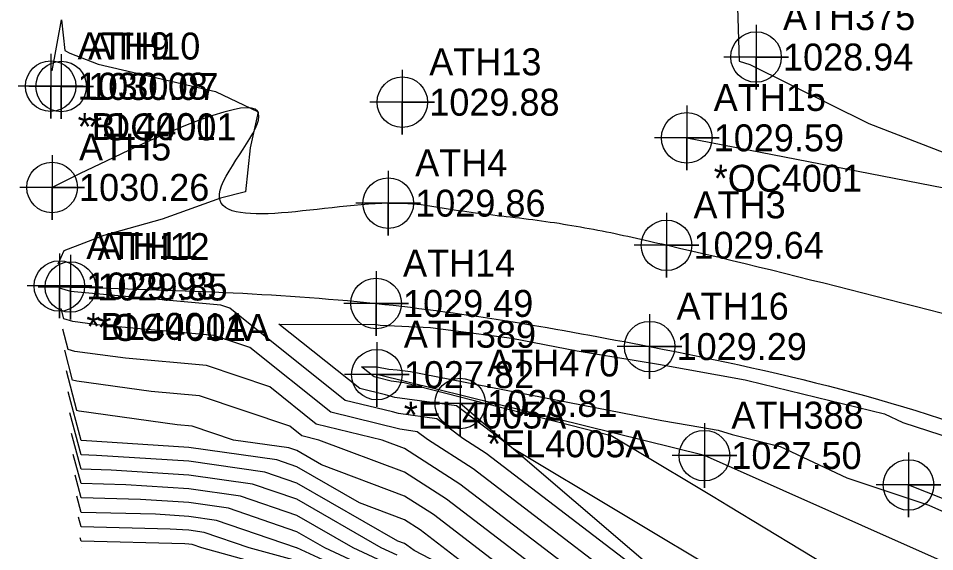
# Model space of a CAD drawing. Extents: x 1213164 to 1213550, y 766120 to 766870.
# Drawn here: x 1213164.2 to 1213249.2, y 766399.6 to 766449.1 of the extents above; entities that cross this region are included whole.
import ezdxf

# ---------------------------------------------------------------- set-up
doc = ezdxf.new("R2010")
doc.units = 0
for name, color, linetype in [('Default', 7, 'Continuous'), ('Exist DTM Breakline', 7, 'Continuous'), ('Exist DTM Breakline Cogo Comment', 7, 'Continuous'), ('Exist DTM Breakline Cogo Elevation', 7, 'Continuous'), ('Exist DTM Breakline Cogo Number', 7, 'Continuous'), ('Exist DTM Breakline Cogo Point CELL', 7, 'Continuous'), ('Exist DTM Crownline', 7, 'Continuous'), ('Exist DTM Crownline Cogo Point CELL', 7, 'Continuous'), ('Exist DTM QL2 LIDAR Elevation Point', 7, 'Continuous'), ('Exist DTM Regular Point CELL', 7, 'Continuous'), ('Exist DTM Regular Point Cogo Comment', 7, 'Continuous'), ('Exist DTM Regular Point Cogo Elevation', 7, 'Continuous'), ('Exist DTM Regular Point Cogo Number', 7, 'Continuous'), ('Exist DTM Regular Point Underwater Cogo Elevation', 7, 'Continuous'), ('Exist DTM Regular Point Underwater Cogo Number', 7, 'Continuous'), ('Exist Roads EOP', 7, 'Continuous'), ('Exist Roads EOP Cogo Point CELL', 7, 'Continuous')]:
    doc.layers.add(name, color=color, linetype=linetype)

msp = doc.modelspace()

# ---------------------------------------------------------------- linework, layer by layer
at = {"layer": 'Default'}
for points in [[(1213169.0884030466, 766461.2208687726), (1213170, 766466.2138052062), (1213174.3374099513, 766465.6625900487), (1213179.4609903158, 766470), (1213179.9999999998, 766470.2147953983), (1213188.5500699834, 766471.4499300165), (1213190, 766472.0752139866), (1213197.1412160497, 766472.8587839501), (1213199.9999999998, 766472.7274150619), (1213205.0383873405, 766468.2069825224), (1213205.4026470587, 766466.900882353), (1213205.4678081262, 766465.190751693), (1213227.328634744, 766455.9379532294), (1213230.7239666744, 766455.1990821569), (1213231.0326136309, 766445.1780503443), (1213232.021415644, 766444.8682285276), (1213243.076208, 766439.375128), (1213255.6098, 766434.52024)], [(1213167.3278836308, 766444.266192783), (1213168.191443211, 766448.9960222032), (1213168.490176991, 766446.1676194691), (1213168.9487679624, 766445.9028174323), (1213171.5897251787, 766444.8966020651), (1213182.4647476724, 766442.3584832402), (1213186.425833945, 766440.450790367), (1213185.673768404, 766437.1334413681), (1213185.2370335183, 766433.0329261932), (1213182.9221293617, 766432.4529255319), (1213177.5355962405, 766430.515562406), (1213172.1224636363, 766428.9784461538), (1213168.3923192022, 766427.5680099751), (1213167.8347713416, 766426.335765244)], [(1213230.8081849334, 766390.9638023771), (1213207.5791692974, 766408.7484188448), (1213205.4162893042, 766410.1402613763), (1213202.99428995, 766411.973562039), (1213199.4402524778, 766412.4644380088), (1213198.8978841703, 766412.6065232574), (1213194.4978428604, 766413.673672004), (1213183.790178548, 766422.2496668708), (1213182.9698195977, 766422.526552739), (1213169.360196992, 766423.7519550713), (1213169.0402473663, 766423.7959584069), (1213168.014222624, 766424.0926136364), (1213167.9967245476, 766424.1586071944)], [(1213225.8213471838, 766392.4264672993), (1213206.3523496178, 766407.3323358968), (1213202.1215090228, 766410.0549390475), (1213201.172834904, 766410.7730254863), (1213199.7807522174, 766410.9652969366), (1213199.568311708, 766411.0209503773), (1213193.1545215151, 766412.5764967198), (1213185.6447977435, 766418.5911933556), (1213182.3041347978, 766419.7187270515), (1213171.7451078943, 766420.6694555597), (1213169.233722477, 766421.0148516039), (1213168.4145325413, 766421.2517045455), (1213168.1573347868, 766422.2217194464)], [(1213230.27052591, 766397.0919027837), (1213210.0502904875, 766409.2118387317), (1213208.8059889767, 766410.1645017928), (1213208.711069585, 766410.2255837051), (1213204.8157449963, 766413.1740985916), (1213199.0997527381, 766413.9635790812), (1213198.2274566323, 766414.1920961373), (1213195.841164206, 766414.7708472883), (1213188.354160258, 766420.7673471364), (1213197.3822142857, 766420.732), (1213197.7500768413, 766420.6560518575), (1213202.4220598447, 766420.4321571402), (1213209.9590629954, 766419.4594779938), (1213216.0055279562, 766418.2743214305), (1213223.5451874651, 766417.0549871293), (1213231.5942266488, 766415.6015483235), (1213231.834396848, 766415.5269702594), (1213244.5309932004, 766412.4389489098), (1213246.2129118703, 766411.6392958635), (1213257.9370376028, 766407.8232432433), (1213260.9764697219, 766406.1926104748), (1213265.9803135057, 766403.9173045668), (1213272.2724532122, 766399.7307453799), (1213280.2315516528, 766392.5875649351)], [(1213220.8345094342, 766393.8891322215), (1213205.1255299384, 766405.9162529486), (1213199.9999999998, 766409.2146007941), (1213197.910701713, 766410), (1213191.8112001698, 766411.4793214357), (1213187.499416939, 766414.9327198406), (1213181.6384499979, 766416.9109013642), (1213174.1300187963, 766417.586956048), (1213169.4271975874, 766418.2337448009), (1213168.8148424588, 766418.4107954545), (1213168.3179450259, 766420.284831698)], [(1213215.8476716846, 766395.3517971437), (1213203.898710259, 766404.5001700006), (1213199.9999999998, 766407.0090427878), (1213192.0435343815, 766410), (1213190.4678788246, 766410.3821461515), (1213189.3540361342, 766411.2742463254), (1213180.972765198, 766414.1030756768), (1213176.5149296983, 766414.5044565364), (1213169.6206726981, 766415.4526379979), (1213169.215152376, 766415.5698863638), (1213168.478555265, 766418.3479439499)], [(1213210.8608339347, 766396.8144620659), (1213202.6718905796, 766403.0840870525), (1213199.9999999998, 766404.8034847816), (1213192.303152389, 766407.696847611), (1213190, 766409.0192626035), (1213189.269926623, 766409.269926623), (1213184.144654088, 766410), (1213180.307080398, 766411.2952499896), (1213178.8998406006, 766411.4219570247), (1213169.8141478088, 766412.6715311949), (1213169.6154622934, 766412.7289772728), (1213168.6391655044, 766416.4110562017)], [(1213246.8828537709, 766393.6463803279), (1213230.0550771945, 766403.8675197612), (1213228.6332668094, 766404.7308749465), (1213221.2881558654, 766409.1335078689), (1213219.162730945, 766410.4073467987), (1213199.9615952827, 766415.2966552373), (1213198.759252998, 766415.4627201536), (1213197.5570290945, 766415.7776690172), (1213197.184485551, 766415.8680225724), (1213196.0156283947, 766416.8041849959), (1213197.4250714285, 766416.7986666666), (1213198.5360906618, 766416.5692879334), (1213199.308580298, 766416.5322680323), (1213200.554787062, 766416.3714402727), (1213223.8719317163, 766411.8010892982), (1213226.3885002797, 766411.3941029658), (1213229.0750883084, 766410.9089778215), (1213230.3784289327, 766410.5042622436), (1213234.853970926, 766409.4157367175), (1213241.028069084, 766406.4803174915), (1213248.618107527, 766403.962344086)], [(1213205.8739961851, 766398.2771269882), (1213201.4450709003, 766401.6680041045), (1213199.9999999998, 766402.5979267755), (1213195.8372208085, 766404.1627791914), (1213190, 766407.514371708), (1213188.1496667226, 766408.1496667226), (1213179.9999999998, 766409.3105522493), (1213170.0538678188, 766409.9461321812), (1213170, 766409.9475526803), (1213168.7997757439, 766414.4741684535)], [(1213225.6216148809, 766386.8459599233), (1213200.8871584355, 766399.7397919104), (1213200.2182512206, 766400.2519211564), (1213199.9999999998, 766400.3923687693), (1213199.371289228, 766400.6287107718), (1213190, 766406.0094808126), (1213187.0294068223, 766407.0294068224), (1213179.9999999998, 766408.0307160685), (1213171.4210713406, 766408.5789286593), (1213170, 766408.6164024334), (1213168.9603859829, 766412.5372807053)], [(1213199.317832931, 766399.317832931), (1213197.8453111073, 766400), (1213190, 766404.5045899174), (1213185.909146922, 766405.9091469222), (1213179.9999999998, 766406.7508798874), (1213172.7882748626, 766407.2117251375), (1213170, 766407.2852521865), (1213169.1209962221, 766410.6003929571)], [(1213198.4880469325, 766398.4880469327), (1213195.2243539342, 766400), (1213190, 766402.9996990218), (1213184.7888870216, 766404.7888870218), (1213179.9999999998, 766405.4710437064), (1213174.1554783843, 766405.8445216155), (1213170, 766405.9541019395), (1213169.2816064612, 766408.663505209)], [(1213197.6582609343, 766397.6582609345), (1213192.6033967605, 766400), (1213190, 766401.4948081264), (1213183.6686271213, 766403.6686271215), (1213179.9999999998, 766404.1912075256), (1213175.5226819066, 766404.4773180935), (1213170, 766404.6229516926), (1213169.4422167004, 766406.7266174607)], [(1213196.828474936, 766396.8284749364), (1213190, 766399.9918648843), (1213189.9706333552, 766400), (1213182.548367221, 766402.5483672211), (1213179.9999999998, 766402.9113713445), (1213176.8898854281, 766403.1101145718), (1213170, 766403.2918014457), (1213169.6028269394, 766404.7897297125)], [(1213248.618107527, 766403.962344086), (1213263.0023333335, 766397.5598888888)], [(1213190, 766398.7776685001), (1213185.587552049, 766400), (1213181.4281073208, 766401.4281073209), (1213179.9999999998, 766401.6315351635), (1213178.2570889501, 766401.7429110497), (1213170, 766401.9606511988), (1213169.7634371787, 766402.8528419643)], [(1213190, 766397.563472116), (1213181.2044707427, 766400), (1213180.3078474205, 766400.3078474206), (1213179.9999999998, 766400.3516989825), (1213179.624292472, 766400.3757075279), (1213170, 766400.6295009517), (1213169.924047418, 766400.9159542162)]]:
    msp.add_lwpolyline(points, dxfattribs=at)
at = {"layer": 'Exist DTM Breakline'}
for points in [[(1213422.776, 766171.2540000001), (1213409.831, 766196.926), (1213386.6570000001, 766233.346), (1213364.3260000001, 766270.025), (1213348.91, 766295.975), (1213348.91, 766295.975), (1213325.2750000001, 766332.542), (1213305.812, 766359.242), (1213281.253, 766381.475), (1213256.992, 766395.586), (1213227.813, 766408.558), (1213197.433, 766416.071)], [(1213251.9070000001, 766381.433), (1213231.636, 766390.721), (1213205.16, 766413.4010000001)], [(1213246.745, 766405.836), (1213265.533, 766398.3910000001), (1213284.1840000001, 766386.845), (1213308.1400000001, 766364.949), (1213319.74, 766349.721)]]:
    msp.add_lwpolyline(points, dxfattribs=at)
at = {"layer": 'Exist DTM Breakline Cogo Point CELL'}
for points in [[(1213197.433, 766419.071), (1213197.433, 766413.071), (1213197.433, 766416.071), (1213200.433, 766416.071), (1213194.433, 766416.071)], [(1213205.16, 766416.4010000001), (1213205.16, 766410.4010000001), (1213205.16, 766413.4010000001), (1213208.16, 766413.4010000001), (1213202.16, 766413.4010000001)], [(1213227.813, 766411.558), (1213227.813, 766405.558), (1213227.813, 766408.558), (1213230.813, 766408.558), (1213224.813, 766408.558)], [(1213246.745, 766408.836), (1213246.745, 766402.836), (1213246.745, 766405.836), (1213249.745, 766405.836), (1213243.745, 766405.836)]]:
    msp.add_lwpolyline(points, dxfattribs=at)
for centre in [(1213197.433, 766416.071), (1213205.16, 766413.4010000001), (1213227.813, 766408.558), (1213246.745, 766405.836)]:
    msp.add_circle(centre, 2.344041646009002, dxfattribs=at)
at = {"layer": 'Exist DTM Crownline'}
msp.add_spline([(1213263.045, 766418.285), (1213224.299, 766428.074), (1213217.9282366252, 766429.4550394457), (1213211.4867235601, 766430.48415642), (1213204.999098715, 766431.2859451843), (1213198.49, 766431.985), (1213182.9002335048, 766433.2004959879), (1213167.31, 766433.447), (1213167.31, 766433.4469999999)], degree=3, dxfattribs=at)
at = {"layer": 'Exist DTM Crownline Cogo Point CELL'}
for points in [[(1213167.31, 766436.447), (1213167.31, 766430.447), (1213167.31, 766433.447), (1213170.31, 766433.447), (1213164.31, 766433.447)], [(1213198.49, 766434.985), (1213198.49, 766428.985), (1213198.49, 766431.985), (1213201.49, 766431.985), (1213195.49, 766431.985)], [(1213224.299, 766431.074), (1213224.299, 766425.074), (1213224.299, 766428.074), (1213227.299, 766428.074), (1213221.299, 766428.074)]]:
    msp.add_lwpolyline(points, dxfattribs=at)
for centre in [(1213167.31, 766433.447), (1213198.49, 766431.985), (1213224.299, 766428.074)]:
    msp.add_circle(centre, 2.344041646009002, dxfattribs=at)
at = {"layer": 'Exist DTM QL2 LIDAR Elevation Point'}
for p, q in [((1213170, 766410), (1213170, 766410)), ((1213180, 766410), (1213180, 766410)), ((1213190, 766410), (1213190, 766410)), ((1213200, 766410), (1213200, 766410)), ((1213170, 766400), (1213170, 766400)), ((1213180, 766400), (1213180, 766400)), ((1213190, 766400), (1213190, 766400)), ((1213200, 766400), (1213200, 766400))]:
    msp.add_line(p, q, dxfattribs=at)
at = {"layer": 'Exist DTM Regular Point CELL'}
msp.add_lwpolyline([(1213232.6030000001, 766448.547), (1213232.6030000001, 766442.547), (1213232.6030000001, 766445.547), (1213235.6030000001, 766445.547), (1213229.6030000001, 766445.547)], dxfattribs=at)
msp.add_circle((1213232.6030000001, 766445.547), 2.344041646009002, dxfattribs=at)
at = {"layer": 'Exist Roads EOP'}
for p, q in [((1213167.18, 766442.8420000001), (1213168.156, 766442.813)), ((1213226.176, 766438.046), (1213254.7920000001, 766432.471)), ((1213167.985, 766424.3), (1213169.012, 766424.202))]:
    msp.add_line(p, q, dxfattribs=at)
msp.add_spline([(1213169.012, 766424.202), (1213197.361, 766422.679), (1213222.732, 766418.674), (1213259.828, 766408.159), (1213283.389, 766394.331), (1213303.908, 766375.84), (1213322.371, 766351.308)], degree=3, dxfattribs=at)
at = {"layer": 'Exist Roads EOP Cogo Point CELL'}
for points in [[(1213167.18, 766445.8420000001), (1213167.18, 766439.8420000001), (1213167.18, 766442.8420000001), (1213170.18, 766442.8420000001), (1213164.18, 766442.8420000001)], [(1213168.156, 766445.813), (1213168.156, 766439.813), (1213168.156, 766442.813), (1213171.156, 766442.813), (1213165.156, 766442.813)], [(1213199.794, 766444.354), (1213199.794, 766438.354), (1213199.794, 766441.354), (1213202.794, 766441.354), (1213196.794, 766441.354)], [(1213226.176, 766441.046), (1213226.176, 766435.046), (1213226.176, 766438.046), (1213229.176, 766438.046), (1213223.176, 766438.046)], [(1213167.985, 766427.3), (1213167.985, 766421.3), (1213167.985, 766424.3), (1213170.985, 766424.3), (1213164.985, 766424.3)], [(1213169.012, 766427.202), (1213169.012, 766421.202), (1213169.012, 766424.202), (1213172.012, 766424.202), (1213166.012, 766424.202)], [(1213197.361, 766425.679), (1213197.361, 766419.679), (1213197.361, 766422.679), (1213200.361, 766422.679), (1213194.361, 766422.679)], [(1213222.732, 766421.674), (1213222.732, 766415.674), (1213222.732, 766418.674), (1213225.732, 766418.674), (1213219.732, 766418.674)]]:
    msp.add_lwpolyline(points, dxfattribs=at)
for centre in [(1213167.18, 766442.8420000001), (1213168.156, 766442.813), (1213199.794, 766441.354), (1213226.176, 766438.046), (1213167.985, 766424.3), (1213169.012, 766424.202), (1213197.361, 766422.679), (1213222.732, 766418.674)]:
    msp.add_circle(centre, 2.344041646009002, dxfattribs=at)

# ---------------------------------------------------------------- texts
at = {"layer": 'Exist DTM Breakline Cogo Comment'}
for p in [(1213199.933, 766411.071), (1213207.66, 766408.4010000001)]:
    msp.add_text('*EL4005A', height=2.5, dxfattribs=at).set_placement(p)
at = {"layer": 'Exist DTM Breakline Cogo Elevation'}
for s, p in [('1027.82', (1213199.933, 766414.821)), ('1028.81', (1213207.66, 766412.1510000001)), ('1027.50', (1213230.313, 766407.308))]:
    msp.add_text(s, height=2.5, dxfattribs=at).set_placement(p)
at = {"layer": 'Exist DTM Breakline Cogo Number'}
for s, p in [('ATH389', (1213199.933, 766418.571)), ('ATH470', (1213207.66, 766415.9010000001)), ('ATH388', (1213230.313, 766411.058))]:
    msp.add_text(s, height=2.5, dxfattribs=at).set_placement(p)
at = {"layer": 'Exist DTM Regular Point Cogo Comment'}
for s, p in [('*BL4001', (1213169.68, 766437.8420000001)), ('*OC4001', (1213170.656, 766437.813)), ('*OC4001', (1213228.676, 766433.046)), ('*BL4001A', (1213170.485, 766419.3)), ('*OC4001A', (1213171.512, 766419.202))]:
    msp.add_text(s, height=2.5, dxfattribs=at).set_placement(p)
at = {"layer": 'Exist DTM Regular Point Cogo Elevation'}
for s, p in [('1028.94', (1213235.1030000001, 766444.297)), ('1030.08', (1213169.68, 766441.5920000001)), ('1030.07', (1213170.656, 766441.563)), ('1029.88', (1213202.294, 766440.104)), ('1029.59', (1213228.676, 766436.796)), ('1029.93', (1213170.485, 766423.05)), ('1029.85', (1213171.512, 766422.952)), ('1029.49', (1213199.861, 766421.429)), ('1029.29', (1213225.232, 766417.424))]:
    msp.add_text(s, height=2.5, dxfattribs=at).set_placement(p)
at = {"layer": 'Exist DTM Regular Point Cogo Number'}
for s, p in [('ATH375', (1213235.1030000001, 766448.047)), ('ATH9', (1213169.68, 766445.3420000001)), ('ATH10', (1213170.656, 766445.313)), ('ATH13', (1213202.294, 766443.854)), ('ATH15', (1213228.676, 766440.546)), ('ATH11', (1213170.485, 766426.8)), ('ATH12', (1213171.512, 766426.702)), ('ATH14', (1213199.861, 766425.179)), ('ATH16', (1213225.232, 766421.174))]:
    msp.add_text(s, height=2.5, dxfattribs=at).set_placement(p)
at = {"layer": 'Exist DTM Regular Point Underwater Cogo Elevation'}
for s, p in [('1030.26', (1213169.81, 766432.197)), ('1029.86', (1213200.99, 766430.735)), ('1029.64', (1213226.799, 766426.824))]:
    msp.add_text(s, height=2.5, dxfattribs=at).set_placement(p)
at = {"layer": 'Exist DTM Regular Point Underwater Cogo Number'}
for s, p in [('ATH5', (1213169.81, 766435.947)), ('ATH4', (1213200.99, 766434.485)), ('ATH3', (1213226.799, 766430.574))]:
    msp.add_text(s, height=2.5, dxfattribs=at).set_placement(p)

doc.saveas('drawing.dxf')
